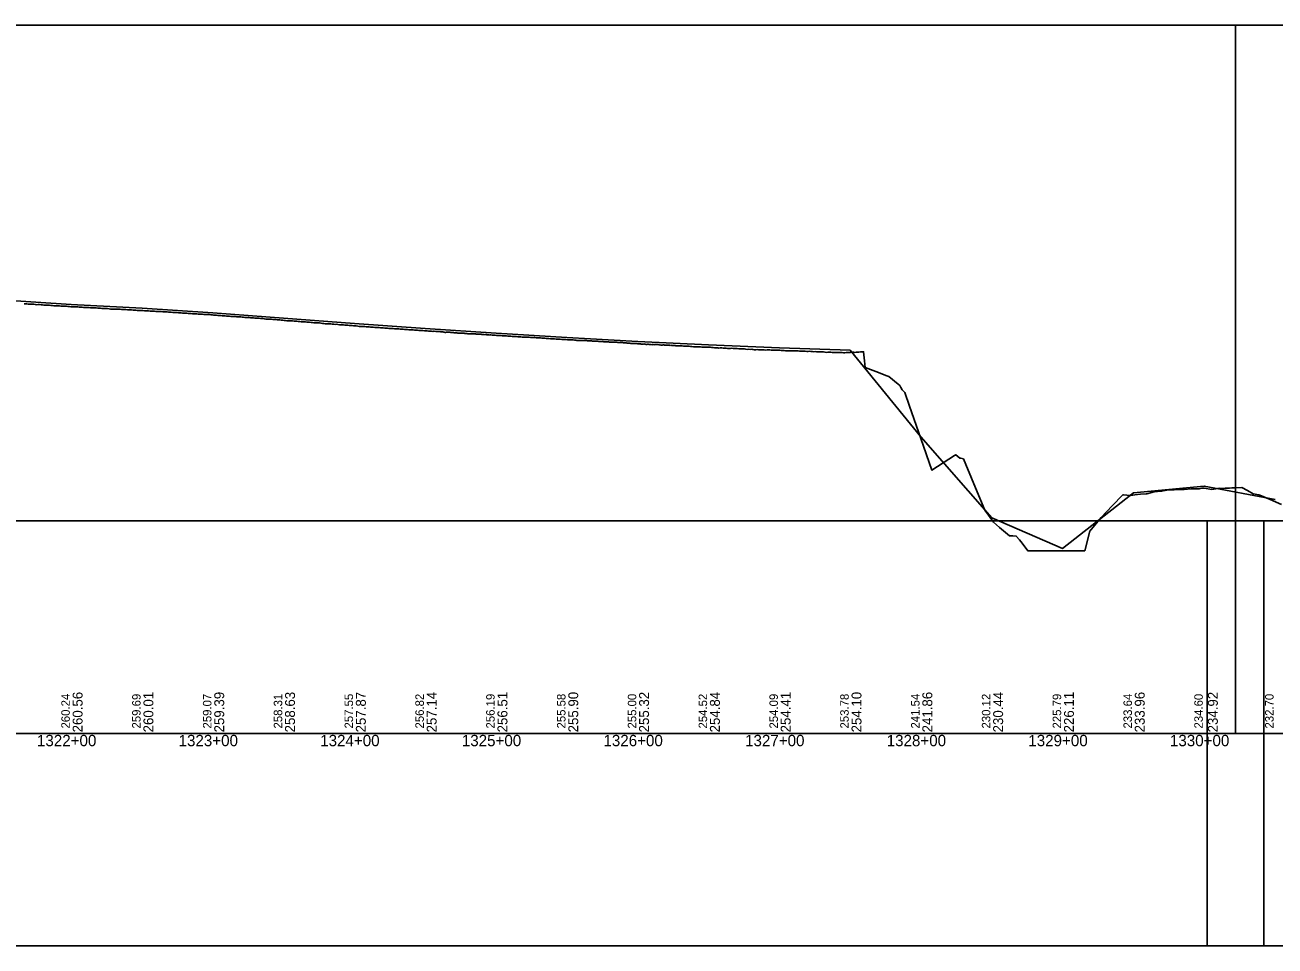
# Model space of a CAD drawing. Extents: x 2898 to 49495, y -15038 to -13538.
# Drawn here: x 21621 to 22503, y -15038 to -14388 of the extents above; entities that cross this region are included whole.
import ezdxf

# ---------------------------------------------------------------- set-up
doc = ezdxf.new("R2010")
doc.units = 0
for name, color, linetype in [('RD_DDB_Profile_EX', 7, 'Continuous'), ('RD_DDB_Profile_PR', 7, 'Continuous'), ('RD_DDB_StaTX', 7, 'Continuous'), ('RD_DDB_StripGrade', 7, 'Continuous'), ('RD_GPK_Profile_Cell', 7, 'Continuous'), ('RD_SHT_ShtClip', 7, 'Continuous')]:
    doc.layers.add(name, color=color, linetype=linetype)

msp = doc.modelspace()

# ---------------------------------------------------------------- linework, layer by layer
at = {"layer": 'RD_DDB_Profile_EX'}
for points in [[(21620.07, -14585.18), (21621.07, -14585.28), (21622.07, -14585.31), (21623.07, -14585.37), (21624.07, -14585.45), (21625.07, -14585.47), (21626.07, -14585.47), (21627.07, -14585.53), (21628.07, -14585.79), (21629.07, -14585.84), (21630.07, -14585.83), (21631.07, -14585.83), (21632.06, -14585.88), (21633.06, -14586), (21634.06, -14586.12), (21635.06, -14586.11), (21636.06, -14586.18), (21637.06, -14586.18), (21638.06, -14586.28), (21639.07, -14586.38), (21640.06, -14586.44), (21641.06, -14586.55), (21642.06, -14586.57), (21643.06, -14586.64), (21644.06, -14586.7), (21645.06, -14586.73), (21646.06, -14586.82), (21647.06, -14586.9), (21648.06, -14586.93), (21649.06, -14586.97), (21650.06, -14586.97), (21651.06, -14587.09), (21652.05, -14587.22), (21653.05, -14587.27), (21654.05, -14587.25), (21655.05, -14587.27), (21656.06, -14587.31), (21657.06, -14587.38), (21658.05, -14587.48), (21659.05, -14587.52), (21660.05, -14587.58), (21661.05, -14587.66), (21662.05, -14587.78), (21663.06, -14587.81), (21664.06, -14587.8), (21665.05, -14587.84), (21666.05, -14587.89), (21667.06, -14587.98), (21668.05, -14588.1), (21669.05, -14588.13), (21670.05, -14588.12), (21671.05, -14588.17), (21672.05, -14588.33), (21673.05, -14588.38), (21674.06, -14588.39), (21675.06, -14588.53), (21676.05, -14588.57), (21677.05, -14588.59), (21678.05, -14588.62), (21679.05, -14588.66), (21680.05, -14588.72), (21681.05, -14588.97), (21682.06, -14588.97), (21683.05, -14588.93), (21684.05, -14588.97), (21685.05, -14588.9), (21686.05, -14589.03), (21687.05, -14589.05), (21688.05, -14589.13), (21689.05, -14589.33), (21690.05, -14589.35), (21691.05, -14589.3), (21692.05, -14589.34), (21693.05, -14589.49), (21694.05, -14589.55), (21695.05, -14589.56), (21696.05, -14589.56), (21697.05, -14589.64), (21698.05, -14589.73), (21699.05, -14589.77), (21700.05, -14589.87), (21701.05, -14589.97), (21702.05, -14589.99), (21703.06, -14589.98), (21704.05, -14590.03), (21705.05, -14590.12), (21706.05, -14590.17), (21707.05, -14590.28), (21708.05, -14590.28), (21709.05, -14590.31)], [(21709.05, -14590.31), (21710.06, -14590.37), (21711.05, -14590.42), (21712.06, -14590.48), (21713.05, -14590.61), (21714.06, -14590.6), (21715.05, -14590.63), (21716.05, -14590.7), (21717.05, -14590.74), (21718.05, -14590.8), (21719.06, -14590.89), (21720.05, -14590.97), (21721.06, -14591.01), (21722.05, -14591.07), (21723.06, -14591.16), (21724.05, -14591.22), (21725.06, -14591.3), (21726.05, -14591.31), (21727.05, -14591.4), (21728.06, -14591.46), (21729.05, -14591.55), (21730.06, -14591.56), (21731.05, -14591.63), (21732.06, -14591.86), (21733.05, -14591.86), (21734.06, -14591.93), (21735.06, -14591.94), (21736.06, -14592), (21737.05, -14592.08), (21738.06, -14592.15), (21739.06, -14592.19), (21740.06, -14592.24), (21741.05, -14592.26), (21742.05, -14592.34), (21743.06, -14592.49), (21744.05, -14592.56), (21745.06, -14592.63), (21746.06, -14592.65), (21747.06, -14592.74), (21748.05, -14592.82), (21749.05, -14592.88), (21750.06, -14592.84), (21751.05, -14592.89), (21752.05, -14593.02), (21753.06, -14593.08), (21754.06, -14593.25), (21755.05, -14593.3), (21756.05, -14593.33), (21757.06, -14593.5), (21758.05, -14593.56), (21759.05, -14593.5), (21760.06, -14593.69), (21761.06, -14593.76), (21762.05, -14593.82), (21763.05, -14593.86), (21764.06, -14593.94), (21765.05, -14594.03), (21766.05, -14594.18), (21767.05, -14594.12), (21768.06, -14594.12), (21769.05, -14594.29), (21770.05, -14594.36), (21771.06, -14594.42), (21772.05, -14594.46), (21773.05, -14594.52), (21774.05, -14594.62), (21775.06, -14594.74), (21776.05, -14594.86), (21777.05, -14594.89), (21778.06, -14594.91), (21779.05, -14595), (21780.05, -14595.05), (21781.05, -14595.09), (21782.05, -14595.2), (21783.05, -14595.33), (21784.05, -14595.38), (21785.06, -14595.43), (21786.01, -14595.48), (21787.01, -14595.6), (21787.69, -14595.64), (21788.7, -14595.69), (21789.7, -14595.76), (21790.69, -14595.96), (21791.7, -14595.98), (21792.7, -14595.99), (21793.69, -14596.09), (21794.7, -14596.18), (21795.7, -14596.19), (21796.69, -14596.28), (21797.7, -14596.36), (21798.7, -14596.45), (21799.7, -14596.52), (21800.7, -14596.56), (21801.7, -14596.7), (21802.7, -14596.84), (21803.7, -14596.98), (21804.7, -14597.01), (21805.7, -14597.17), (21806.7, -14597.27), (21807.7, -14597.22), (21808.7, -14597.24)], [(21808.7, -14597.24), (21809.7, -14597.29), (21810.7, -14597.42), (21811.7, -14597.48), (21812.7, -14597.54), (21813.7, -14597.68), (21814.7, -14597.73), (21815.7, -14597.87), (21816.71, -14597.84), (21817.7, -14597.93), (21818.7, -14598.05), (21819.7, -14598.16), (21820.7, -14598.17), (21821.71, -14598.21), (21822.7, -14598.38), (21823.71, -14598.47), (21824.71, -14598.59), (21825.7, -14598.62), (21826.7, -14598.68), (21827.7, -14598.74), (21828.7, -14598.77), (21829.7, -14598.88), (21830.7, -14599.06), (21831.7, -14599.11), (21832.7, -14599.27), (21833.7, -14599.31), (21834.7, -14599.28), (21835.69, -14599.44), (21836.7, -14599.47), (21837.7, -14599.53), (21838.69, -14599.68), (21839.69, -14599.73), (21840.7, -14599.71), (21841.69, -14599.9), (21842.69, -14600.01), (21843.69, -14599.96), (21844.69, -14600.09), (21845.69, -14600.15), (21846.69, -14600.29), (21847.69, -14600.26), (21848.69, -14600.41), (21849.69, -14600.56), (21850.69, -14600.62), (21851.69, -14600.62), (21852.69, -14600.66), (21853.69, -14600.76), (21854.69, -14600.86), (21855.69, -14601.01), (21856.69, -14601.17), (21857.68, -14601.17), (21858.69, -14601.24), (21859.68, -14601.21), (21860.69, -14601.35), (21861.69, -14601.41), (21862.68, -14601.46), (21863.69, -14601.49), (21864.69, -14601.66), (21865.69, -14601.81), (21866.69, -14601.76), (21867.69, -14601.86), (21868.69, -14601.97), (21869.69, -14602.01), (21870.7, -14602.04), (21871.7, -14602.1), (21872.7, -14602.19), (21873.7, -14602.2), (21874.7, -14602.36), (21875.7, -14602.53), (21876.7, -14602.53), (21877.7, -14602.58), (21878.7, -14602.65), (21879.71, -14602.68), (21880.7, -14602.73), (21881.7, -14602.78), (21882.71, -14602.83), (21883.7, -14602.88), (21884.71, -14602.92), (21885.71, -14603.1), (21886.71, -14603.18), (21887.71, -14603.2), (21888.71, -14603.29), (21889.71, -14603.31), (21890.71, -14603.47), (21891.71, -14603.52), (21892.71, -14603.55), (21893.72, -14603.6), (21894.72, -14603.66), (21895.71, -14603.74), (21896.71, -14603.76), (21897.71, -14603.83), (21898.72, -14604.01), (21899.72, -14604.06), (21900.72, -14604.05), (21901.72, -14604.18), (21902.72, -14604.32), (21903.72, -14604.37), (21904.72, -14604.38), (21905.72, -14604.48), (21906.72, -14604.51), (21907.72, -14604.5), (21908.72, -14604.66)], [(21908.72, -14604.66), (21909.42, -14604.62), (21909.72, -14604.65), (21910.72, -14604.76), (21911.42, -14604.86), (21911.72, -14604.86), (21912.72, -14604.87), (21913.42, -14604.84), (21913.72, -14604.84), (21914.42, -14604.91), (21914.73, -14604.95), (21915.42, -14605.06), (21915.72, -14605.06), (21916.42, -14605.13), (21916.72, -14605.16), (21917.42, -14605.37), (21917.72, -14605.38), (21918.42, -14605.28), (21918.72, -14605.26), (21919.42, -14605.23), (21919.73, -14605.24), (21920.42, -14605.31), (21920.72, -14605.33), (21921.42, -14605.43), (21921.73, -14605.48), (21922.42, -14605.55), (21922.72, -14605.59), (21923.42, -14605.59), (21923.73, -14605.64), (21924.42, -14605.74), (21924.72, -14605.73), (21925.42, -14605.83), (21925.73, -14605.83), (21926.42, -14605.87), (21926.73, -14605.9), (21927.42, -14605.93), (21927.73, -14605.93), (21928.42, -14605.97), (21928.73, -14605.95), (21929.42, -14605.99), (21929.73, -14606.02), (21930.42, -14605.99), (21930.73, -14606.03), (21931.41, -14606.1), (21931.73, -14606.13), (21932.42, -14606.13), (21932.73, -14606.21), (21933.42, -14606.38), (21933.73, -14606.38), (21934.42, -14606.38), (21934.73, -14606.37), (21935.42, -14606.33), (21935.73, -14606.4), (21936.42, -14606.43), (21936.73, -14606.45), (21937.42, -14606.51), (21937.73, -14606.5), (21938.42, -14606.5), (21938.73, -14606.53), (21939.42, -14606.67), (21939.73, -14606.67), (21940.42, -14606.67), (21940.73, -14606.68), (21941.42, -14606.72), (21941.73, -14606.73), (21942.42, -14606.77), (21942.73, -14606.77), (21943.42, -14606.87), (21943.73, -14606.92), (21944.42, -14606.98), (21944.73, -14606.95), (21945.42, -14607.02), (21945.73, -14607.01), (21946.42, -14606.97), (21946.73, -14607.03), (21947.42, -14607.21), (21947.73, -14607.24), (21948.42, -14607.24), (21948.72, -14607.25), (21949.41, -14607.22), (21949.72, -14607.2), (21950.72, -14607.39), (21951.71, -14607.45), (21952.71, -14607.46), (21953.71, -14607.53), (21954.71, -14607.6), (21955.71, -14607.63), (21956.71, -14607.7), (21957.71, -14607.72), (21958.71, -14607.77), (21959.71, -14607.83), (21960.71, -14607.89), (21961.71, -14608), (21962.7, -14608.12), (21963.7, -14608.15), (21964.7, -14608.22), (21965.7, -14608.29), (21966.7, -14608.31), (21967.7, -14608.38), (21968.7, -14608.46), (21969.7, -14608.55)], [(21969.7, -14608.55), (21970.69, -14608.49), (21971.69, -14608.73), (21972.69, -14608.79), (21973.42, -14608.75), (21974.69, -14608.79), (21975.69, -14608.88), (21976.69, -14608.89), (21977.68, -14608.96), (21978.68, -14608.99), (21979.68, -14609.08), (21980.68, -14609.1), (21981.68, -14609.24), (21982.68, -14609.24), (21983.68, -14609.29), (21984.68, -14609.36), (21985.68, -14609.43), (21986.69, -14609.54), (21987.69, -14609.59), (21988.68, -14609.7), (21989.69, -14609.74), (21990.69, -14609.8), (21991.69, -14609.91), (21992.69, -14609.94), (21993.69, -14609.97), (21994.69, -14610.06), (21995.69, -14610.09), (21996.69, -14610.29), (21997.7, -14610.25), (21998.7, -14610.25), (21999.7, -14610.41), (22000.71, -14610.45), (22001.7, -14610.47), (22002.7, -14610.5), (22003.7, -14610.56), (22004.71, -14610.65), (22005.71, -14610.62), (22006.71, -14610.64), (22007.41, -14610.68), (22007.71, -14610.68), (22008.71, -14610.79), (22009.41, -14611), (22009.71, -14611), (22010.41, -14611.07), (22010.71, -14611.05), (22011.41, -14611.02), (22011.72, -14611.02), (22012.41, -14611.05), (22012.72, -14611.11), (22013.41, -14611.11), (22013.72, -14611.14), (22014.41, -14611.21), (22014.72, -14611.2), (22015.41, -14611.16), (22015.72, -14611.15), (22016.41, -14611.22), (22016.72, -14611.22), (22017.41, -14611.22), (22017.72, -14611.25), (22018.41, -14611.32), (22018.72, -14611.32), (22019.41, -14611.35), (22019.72, -14611.38), (22020.41, -14611.42), (22020.72, -14611.46), (22021.41, -14611.5), (22021.72, -14611.5), (22022.72, -14611.63), (22023.41, -14611.63), (22023.73, -14611.67), (22024.41, -14611.67), (22024.73, -14611.7), (22025.41, -14611.7), (22025.72, -14611.73), (22026.41, -14611.8), (22026.72, -14611.81), (22027.41, -14611.95), (22027.73, -14611.95), (22028.41, -14611.95), (22028.73, -14611.95), (22029.41, -14611.98), (22029.73, -14611.98), (22030.41, -14611.98), (22030.73, -14612.05), (22031.41, -14612.01), (22031.73, -14612.03), (22032.41, -14612.06), (22032.72, -14612.11), (22033.41, -14612.35), (22033.72, -14612.38), (22034.41, -14612.38), (22034.73, -14612.4), (22035.41, -14612.33), (22035.72, -14612.3), (22036.41, -14612.26), (22036.73, -14612.26), (22037.41, -14612.4), (22037.73, -14612.4), (22038.41, -14612.37), (22038.73, -14612.37), (22039.41, -14612.43)], [(22039.41, -14612.43), (22039.73, -14612.45), (22040.4, -14612.48), (22040.72, -14612.55), (22041.41, -14612.58), (22041.73, -14612.6), (22042.41, -14612.6), (22042.72, -14612.57), (22043.41, -14612.67), (22043.72, -14612.68), (22044.41, -14612.72), (22044.72, -14612.77), (22045.41, -14612.83), (22045.72, -14612.91), (22046.41, -14612.95), (22046.72, -14612.95), (22047.4, -14613.08), (22047.72, -14613.1), (22048.41, -14613.17), (22048.72, -14613.17), (22049.4, -14613.13), (22049.72, -14613.18), (22050.41, -14613.15), (22050.72, -14613.19), (22051.41, -14613.23), (22051.72, -14613.2), (22052.41, -14613.23), (22052.72, -14613.26), (22053.41, -14613.47), (22053.72, -14613.45), (22054.41, -14613.45), (22054.72, -14613.52), (22055.4, -14613.58), (22055.71, -14613.63), (22056.41, -14613.63), (22056.72, -14613.68), (22057.4, -14613.61), (22057.72, -14613.52), (22058.41, -14613.72), (22058.72, -14613.8), (22059.4, -14613.94), (22059.72, -14613.92), (22060.41, -14613.82), (22060.72, -14613.79), (22061.4, -14613.86), (22061.72, -14613.95), (22062.41, -14613.98), (22062.72, -14613.98), (22063.41, -14614.09), (22063.72, -14614.06), (22064.41, -14614.06), (22064.72, -14614.1), (22065.41, -14613.97), (22065.72, -14613.95), (22066.41, -14613.98), (22066.72, -14614), (22067.4, -14614.03), (22067.71, -14614.05), (22068.41, -14614.29), (22068.72, -14614.31), (22069.4, -14614.27), (22069.71, -14614.37), (22070.41, -14614.37), (22070.72, -14614.37), (22071.4, -14614.3), (22071.71, -14614.27), (22072.41, -14614.4), (22072.71, -14614.48), (22073.41, -14614.48), (22073.71, -14614.5), (22074.4, -14614.46), (22074.71, -14614.43), (22075.41, -14614.5), (22075.71, -14614.52), (22076.4, -14614.55), (22076.71, -14614.52), (22077.41, -14614.59), (22077.71, -14614.6), (22078.4, -14614.6), (22078.71, -14614.64), (22079.71, -14614.76), (22080.4, -14614.79), (22080.7, -14614.81), (22081.4, -14614.95), (22081.7, -14614.86), (22082.7, -14614.94), (22083.7, -14614.95), (22084.7, -14615), (22085.7, -14615.08), (22086.7, -14615.15), (22087.7, -14615.09), (22088.69, -14615.13), (22089.7, -14615.18), (22090.7, -14615.3), (22091.7, -14615.4), (22092.69, -14615.54), (22093.69, -14615.55), (22094.07, -14615.57), (22094.69, -14615.64), (22095.69, -14615.69), (22096.69, -14615.69)], [(22096.69, -14615.69), (22097.69, -14615.7), (22098.69, -14615.77), (22099.69, -14615.77), (22100.7, -14615.83), (22101.7, -14615.83), (22102.03, -14615.86), (22102.69, -14615.89), (22103.69, -14615.87), (22104.69, -14615.89), (22105.7, -14616.09), (22106.7, -14616.09), (22107.7, -14616.19), (22108.7, -14616.2), (22109.99, -14616.4), (22110.7, -14616.44), (22111.7, -14616.34), (22112.7, -14616.42), (22113.7, -14616.52), (22114.7, -14616.5), (22115.69, -14616.53), (22116.7, -14616.71), (22117.95, -14616.77), (22118.7, -14616.81), (22119.7, -14616.57), (22120.7, -14616.69), (22121.69, -14616.75), (22122.7, -14616.79), (22123.7, -14616.86), (22124.7, -14616.95), (22125.9, -14616.95), (22126.7, -14616.95), (22127.7, -14617.11), (22128.69, -14617.11), (22129.69, -14617.3), (22130.7, -14617.37), (22131.7, -14617.36), (22132.69, -14617.41), (22133.86, -14617.32), (22134.7, -14617.39), (22135.69, -14617.61), (22136.7, -14617.65), (22137.69, -14617.56), (22138.69, -14617.71), (22139.69, -14617.78), (22140.7, -14617.68), (22141.82, -14617.68), (22142.69, -14617.82), (22143.69, -14617.87), (22144.69, -14617.77), (22145.7, -14617.74), (22146.69, -14617.75), (22147.69, -14617.86), (22148.69, -14617.86), (22149.78, -14617.9), (22150.69, -14617.93), (22151.69, -14617.98), (22152.69, -14618.06), (22153.69, -14618), (22154.69, -14618.15), (22155.69, -14618.2), (22156.69, -14618.23), (22157.73, -14618.38), (22158.69, -14618.38), (22159.69, -14618.39), (22160.69, -14618.39), (22161.69, -14618.41), (22162.69, -14618.44), (22163.68, -14618.43), (22164.69, -14618.52), (22165.69, -14618.52), (22166.68, -14618.51), (22167.69, -14618.65), (22168.68, -14618.73), (22169.69, -14618.72), (22170.68, -14618.64), (22171.68, -14618.77), (22172.68, -14618.86), (22173.68, -14618.85), (22174.68, -14618.73), (22175.69, -14618.87), (22176.68, -14618.91), (22177.68, -14619.02), (22178.68, -14618.94), (22179.68, -14619.05), (22180.68, -14619.14), (22181.68, -14619.14), (22182.67, -14619.2), (22183.68, -14619.22), (22184.67, -14619.23), (22185.68, -14619.41), (22186.68, -14619.54), (22187.67, -14619.37), (22188.67, -14619.41), (22189.67, -14619.44), (22190.67, -14619.48), (22191.67, -14619.54), (22192.67, -14619.57), (22193.66, -14619.64), (22194.66, -14619.62), (22195.67, -14619.56)], [(22195.67, -14619.56), (22196.66, -14619.58), (22197.67, -14619.71), (22198.66, -14619.77), (22199.66, -14619.75), (22200.66, -14619.71), (22201.66, -14619.64), (22202.66, -14619.63), (22203.66, -14619.55), (22204.65, -14619.44), (22205.65, -14619.42), (22206.4, -14619.5), (22207.64, -14619.4), (22208.63, -14619.37), (22209.63, -14619.25), (22210.63, -14619.23), (22211.63, -14619.21), (22212.83, -14619.02), (22213.44, -14625.37), (22213.88, -14630.11), (22221.4, -14633), (22229.35, -14636.06), (22230.7, -14636.57), (22237.31, -14642.03), (22238.42, -14642.94), (22239.23, -14644.4), (22240.03, -14645.88), (22241.96, -14647.92), (22245.27, -14657.43), (22253.23, -14680.31), (22260.96, -14702.56), (22269.14, -14697.4), (22277.1, -14692.38), (22278.04, -14691.78), (22280.83, -14694.1), (22281.63, -14694.19), (22283.41, -14694.66), (22285.06, -14698.64), (22293.01, -14717.82), (22298.47, -14730.98), (22300.97, -14734.48), (22304.53, -14739.45), (22308.93, -14743.09), (22315.96, -14748.92), (22316.89, -14748.91), (22318.26, -14748.89), (22320.62, -14749.18), (22323.04, -14751.78), (22324.84, -14754.23), (22328.76, -14759.52), (22332.8, -14759.52), (22340.76, -14759.52), (22343.62, -14759.52), (22348.72, -14759.52), (22356.68, -14759.52), (22364.63, -14759.52), (22369.07, -14759.52), (22372.59, -14745.6), (22380.55, -14735.99), (22388.51, -14727.76), (22395.89, -14720.13), (22396.46, -14720.16), (22401.2, -14720.45), (22402.96, -14720.32), (22404.42, -14720.14), (22408.29, -14719.66), (22412.38, -14719.37), (22412.77, -14719.34), (22418.02, -14717.98), (22420.34, -14717.79), (22423.31, -14717.55), (22428.29, -14716.62), (22428.64, -14716.55), (22430.38, -14716.47), (22432.12, -14716.45), (22436.25, -14716.32), (22437.46, -14716.28), (22439.16, -14716.4), (22444.21, -14715.77), (22444.53, -14715.73), (22449.94, -14715.82), (22451.61, -14715.3), (22452.17, -14715.35), (22453.26, -14715.44), (22458.68, -14716.19), (22460.13, -14715.95), (22464.14, -14715.29), (22465.76, -14715.48), (22468.08, -14715.43), (22471.24, -14715.38), (22472.83, -14715.2), (22474.41, -14715.21), (22476.04, -14715.07), (22479.91, -14714.76), (22484, -14717.05), (22487.9, -14719.23), (22491.96, -14720.09), (22492.73, -14720.25), (22499.91, -14723.43), (22507.87, -14726.96)]]:
    msp.add_lwpolyline(points, dxfattribs=at)
at = {"layer": 'RD_DDB_Profile_PR'}
msp.add_lwpolyline([(21603.38, -14582.47), (21653.38, -14585.66), (21703.38, -14588.4), (21753.38, -14591.54), (21803.38, -14595.33), (21853.38, -14599.13), (21903.38, -14602.76), (21953.38, -14605.91), (22003.38, -14608.94), (22053.38, -14611.86), (22103.38, -14614.28), (22153.38, -14616.42), (22203.38, -14617.97), (22253.38, -14679.15), (22303.38, -14736.25), (22353.38, -14757.92), (22403.38, -14718.66), (22453.38, -14713.86), (22503.38, -14723.37)], dxfattribs=at)
at = {"layer": 'RD_GPK_Profile_Cell'}
msp.add_line((2976.05, -14888.47), (48721.13, -14888.47), dxfattribs=at)
at = {"layer": 'RD_SHT_ShtClip'}
for points in [[(20975.38, -14388.47), (20975.38, -14888.47), (22475.38, -14888.47), (22475.38, -14888.47), (22475.38, -14388.47), (22475.38, -14388.47)], [(22475.38, -14388.47), (22475.38, -14888.47), (23975.38, -14888.47), (23975.38, -14888.47), (23975.38, -14388.47), (23975.38, -14388.47)], [(20955.38, -14738.47), (22495.38, -14738.47), (22495.38, -15038.47), (20955.38, -15038.47)], [(22455.38, -14738.47), (23995.38, -14738.47), (23995.38, -15038.47), (22455.38, -15038.47)]]:
    msp.add_lwpolyline(points, close=True, dxfattribs=at)

# ---------------------------------------------------------------- texts
at = {"layer": 'RD_DDB_StaTX'}
for s, p in [('1322+00', (21629.18, -14897.47)), ('1323+00', (21729.18, -14897.47)), ('1324+00', (21829.18, -14897.47)), ('1325+00', (21929.18, -14897.47)), ('1326+00', (22029.18, -14897.47)), ('1327+00', (22129.18, -14897.47)), ('1328+00', (22229.18, -14897.47)), ('1329+00', (22329.18, -14897.47)), ('1330+00', (22429.18, -14897.47))]:
    msp.add_text(s, height=8, dxfattribs=at).set_placement(p)
at = {"layer": 'RD_DDB_StripGrade'}
for s, height, p in [('260.24', 6, (21652.38, -14884.98)), ('260.56', 7, (21661.38, -14887.72)), ('259.69', 6, (21702.38, -14884.98)), ('260.01', 7, (21711.38, -14887.72)), ('259.07', 6, (21752.38, -14884.98)), ('259.39', 7, (21761.38, -14887.72)), ('258.31', 6, (21802.38, -14884.98)), ('258.63', 7, (21811.38, -14887.72)), ('257.55', 6, (21852.38, -14884.98)), ('257.87', 7, (21861.38, -14887.72)), ('256.82', 6, (21902.38, -14884.98)), ('257.14', 7, (21911.38, -14887.72)), ('256.19', 6, (21952.38, -14884.98)), ('256.51', 7, (21961.38, -14887.72)), ('255.58', 6, (22002.38, -14884.98)), ('255.90', 7, (22011.38, -14887.72)), ('255.00', 6, (22052.38, -14884.98)), ('255.32', 7, (22061.38, -14887.72)), ('254.52', 6, (22102.38, -14884.98)), ('254.84', 7, (22111.38, -14887.72)), ('254.09', 6, (22152.38, -14884.98)), ('254.41', 7, (22161.38, -14887.72)), ('253.78', 6, (22202.38, -14884.98)), ('254.10', 7, (22211.38, -14887.72)), ('241.54', 6, (22252.38, -14884.98)), ('241.86', 7, (22261.38, -14887.72)), ('230.12', 6, (22302.38, -14884.98)), ('230.44', 7, (22311.38, -14887.72)), ('225.79', 6, (22352.38, -14884.98)), ('226.11', 7, (22361.38, -14887.72)), ('233.64', 6, (22402.38, -14884.98)), ('233.96', 7, (22411.38, -14887.72)), ('234.60', 6, (22452.38, -14884.98)), ('234.92', 7, (22462.99, -14887.72)), ('232.70', 6, (22502.38, -14884.98))]:
    msp.add_text(s, height=height, rotation=90, dxfattribs=at).set_placement(p)

doc.saveas('drawing.dxf')
